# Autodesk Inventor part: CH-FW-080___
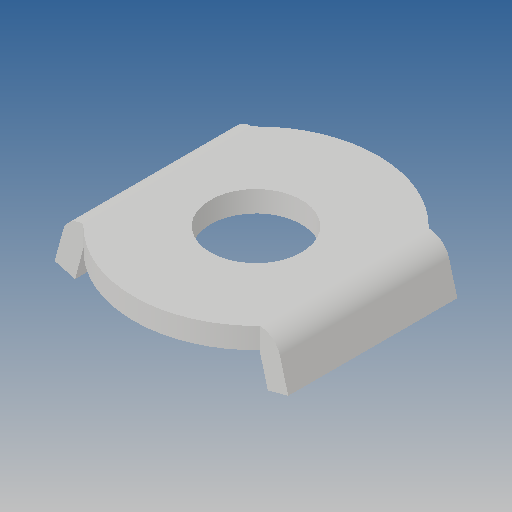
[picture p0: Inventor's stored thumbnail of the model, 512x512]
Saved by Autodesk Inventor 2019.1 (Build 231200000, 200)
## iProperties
Created: 2010-06
Part Number: CH-FW-080___
Material: Ogólny
Document SubType Name: Modeling
Designer: CADENGINEERING4
Density: 1 g/cm^3
Appearance: Domyślna
Author: CADENGINEERING4
Revision Number: ANY
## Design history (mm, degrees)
feature "NONE"
node "Bryła1"
